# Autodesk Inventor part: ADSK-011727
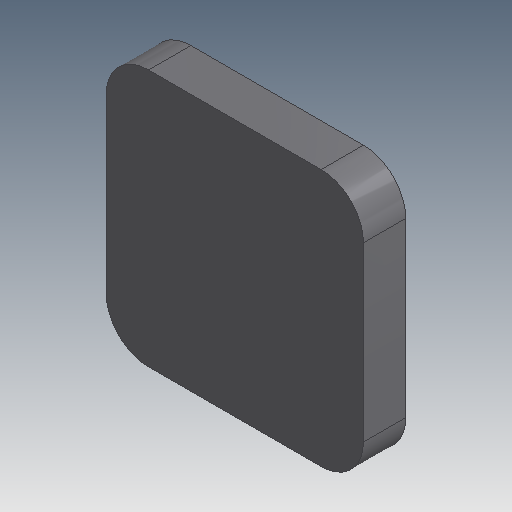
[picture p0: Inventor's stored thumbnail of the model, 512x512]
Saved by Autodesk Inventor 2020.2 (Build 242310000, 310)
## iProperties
Created: 2000-02
Part Number: ADSK-011727
Document SubType Name: Modeling
Designer: sspink
Material: Pearson CRS
Density: 7.83 g/cm^3
Sheet Metal Rule: Standard
Appearance: Metal-Steel(Polish)
Mass: 9.04891 g
Surface Area: 9.55837 cm^2
Volume: 1.15567 cm^3
Control State: 0
Checked Out: False
Master: False
Shininess: 0.0
Length Units: 11272
Angle Units: 11279
Time Units: 11290
Mass Units: 11286
Length Display Precision: 3
Angle Display Precision: 2
Compacted: True
Cutlength: (20.25 X 34.75) 704 SI
Material Desc: SHEET,HRS,11 GA
Material_Number: Axxxxxx
Dimensions: 0,8x0,1x0,8 in
Mass: 0,02 lb
VLT_Material: Pearson CRS
Density: 0.0
Volumn: 0.0
Area: 0.0
PropertySet Name: Model Information
Author: sspink
Revision Number: -
Title: ADSK-011727
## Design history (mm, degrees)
node "Face1"
node "Corner Round1" dims "d3" = 3.175
node "Solide1"
node "Corps solides"
node "Corps surfaciques"
sketch "Sketch1"
  geometry: L1 (0, 0)-(19.304, 0); L2 (19.304, 0)-(19.304, 19.304); L3 (19.304, 19.304)-(0, 19.304); L4 (0, 19.304)-(0, 0)
  constraints: 8 end point, 2 parallel, 1 horizontal, 1 perpendicular
  dimensions: "d0" = 19.304 distance between parallel lines of L2 L4; "d1" = 19.304 distance between parallel lines of L3 L1
node "Plate1" dims "d4" = 3.175 (= Thickness)
other parameters: "Thickness" = 3.175, "BendRadius" = 3.175 (= Thickness), "BendReliefWidth" = 3.175 (= Thickness), "BendReliefDepth" = 1.5875 (= 0.5 x Thickness), "CornerReliefSize" = 7.14375 (= 2.25 x Thickness), "SeamGap" = 0.00508, "MinimumRemnant" = 6.35 (= 2 x Thickness), "d2" = 3.175 (= BendRadius), "TransitionRadius" = 3.175 (= BendRadius), "TailleRayonJacobi" = 3.175 (= Thickness), "TailleJeu" = 3.175 (= Thickness)
